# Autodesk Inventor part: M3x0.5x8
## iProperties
Company: 한국ATC센터
Created: 2009-02
Part Number: M3x0.5x8
Document SubType Name: Modeling
Designer: KYOUNG IL JANG
Density: 1 g/cm^3
Mass: 0.274265 g
Surface Area: 2.99398 cm^2
Volume: 0.274265 cm^3
Vendor: CBT Solutions
Author: KYOUNG IL JANG
